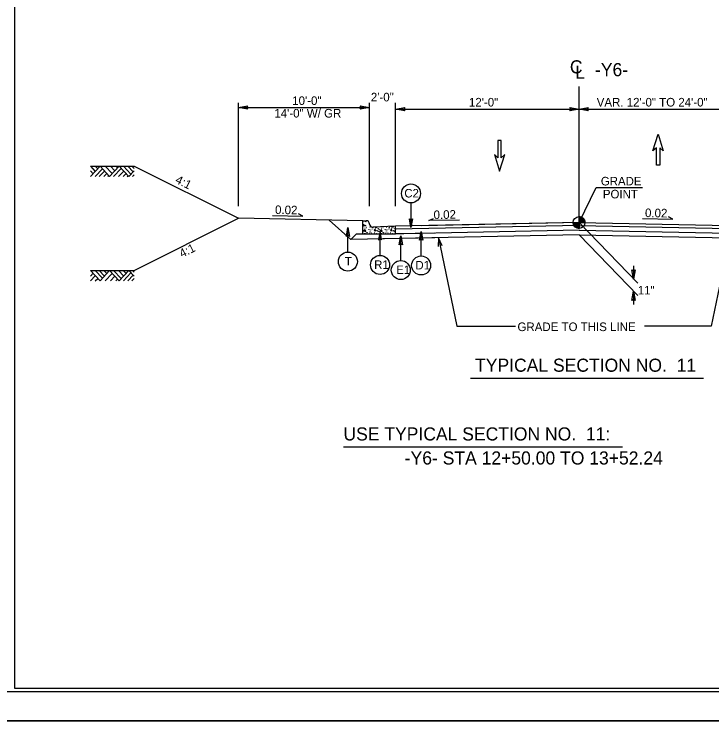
# Model space of a CAD drawing. Extents: x 1901670 to 1902225, y 193498 to 194278.
# Drawn here: x 1901982.5 to 1902035.7, y 193606.9 to 193661.9 of the extents above; entities that cross this region are included whole.
import ezdxf

# ---------------------------------------------------------------- set-up
doc = ezdxf.new("R2010")
doc.units = 0
for name, color, linetype in [('Old_Level_1', 7, 'Continuous'), ('Old_Level_11', 7, 'Continuous'), ('Old_Level_2', 7, 'Continuous'), ('Old_Level_20', 7, 'Continuous'), ('Prop Dimension', 7, 'Continuous'), ('Sheet Border Standard 30in CELL', 7, 'Continuous'), ('Sheet Cutting Line CELL', 7, 'Continuous'), ('Sheet Plot Border Inside CELL', 7, 'Continuous'), ('Sheet Plot Border Outside CELL', 7, 'Continuous'), ('Typical Curb CELL', 7, 'Continuous'), ('Typical Pavement Slope CELL', 7, 'Continuous'), ('Typical Terminator CELL', 7, 'Continuous'), ('Typical Text Grade Point CELL', 7, 'Continuous')]:
    doc.layers.add(name, color=color, linetype=linetype)

# ---------------------------------------------------------------- blocks, each defined once
blk = doc.blocks.new('TERMINATOR')
at = {"layer": 'Typical Terminator CELL'}
blk.add_lwpolyline([(-0.469, 0.081), (0, 0), (-0.471, -0.083), (-0.411, 0)], close=True, dxfattribs=at)

msp = doc.modelspace()

# ---------------------------------------------------------------- linework, layer by layer
at = {"layer": 'Old_Level_1'}
for p, q in [((1902025.621, 193646.02), (1902025.621, 193656.4)), ((1901988.322, 193650.325), (1901988.697, 193649.922)), ((1901988.322, 193649.52), (1901989.064, 193650.317)), ((1901988.696, 193649.52), (1901989.25, 193650.116)), ((1901988.697, 193650.325), (1901988.884, 193650.124)), ((1901989.064, 193650.317), (1901989.788, 193649.538)), ((1901989.455, 193650.325), (1901989.988, 193649.752)), ((1901989.788, 193649.538), (1901990.519, 193650.324)), ((1901989.853, 193650.325), (1901990.186, 193649.966)), ((1901990.098, 193649.52), (1901990.684, 193650.148)), ((1901990.255, 193650.325), (1901990.388, 193650.182)), ((1901990.519, 193650.324), (1901991.26, 193649.528)), ((1901990.841, 193650.325), (1901991.421, 193649.702)), ((1901991.174, 193650.325), (1901991.588, 193649.881)), ((1901991.494, 193650.325), (1901991.664, 193650.142)), ((1901988.322, 193649.963), (1901988.528, 193649.741)), ((1901989.005, 193649.52), (1901989.406, 193649.949)), ((1901989.352, 193649.52), (1901989.579, 193649.763)), ((1901989.663, 193649.52), (1901989.734, 193649.596)), ((1901990.468, 193649.52), (1901990.868, 193649.949)), ((1901990.834, 193649.52), (1901991.051, 193649.753)), ((1901991.129, 193649.52), (1901991.198, 193649.594)), ((1901991.26, 193649.528), (1901991.664, 193649.963)), ((1901991.53, 193649.52), (1901991.664, 193649.663)), ((1902002.236, 193646.566), (1902004.551, 193646.517)), ((1902004.551, 193646.517), (1902004.218, 193646.684)), ((1902006.54, 193646.208), (1902008.199, 193644.724)), ((1902014.167, 193646.163), (1902014.5, 193646.33)), ((1902016.483, 193646.211), (1902014.167, 193646.163)), ((1902025.621, 193646.02), (1902025.621, 193646.47)), ((1902030.469, 193646.331), (1902032.784, 193646.283)), ((1902032.784, 193646.283), (1902032.451, 193646.45)), ((1902025.621, 193646.02), (1902011.621, 193645.74)), ((1902025.621, 193645.801), (1902011.621, 193645.521)), ((1902025.621, 193646.02), (1902013.621, 193645.78)), ((1902025.171, 193646.02), (1902025.621, 193646.02)), ((1902025.62, 193645.57), (1902025.621, 193646.02)), ((1902025.621, 193646.02), (1902025.62, 193645.57)), ((1902026.071, 193646.02), (1902025.621, 193646.02)), ((1902025.621, 193646.02), (1902037.616, 193645.78)), ((1902025.621, 193646.02), (1902030.096, 193641.383)), ((1902025.621, 193645.801), (1902039.84, 193645.517)), ((1902008.622, 193645.147), (1902008.199, 193644.724)), ((1902008.622, 193645.147), (1902009.122, 193645.157)), ((1902025.621, 193645.437), (1902011.026, 193645.145)), ((1902014.623, 193645.217), (1902011.621, 193645.157)), ((1902025.621, 193645.437), (1902040.211, 193645.145)), ((1902014.623, 193644.853), (1902008.199, 193644.724)), ((1902025.621, 193645.073), (1902010.654, 193644.773)), ((1902025.621, 193645.073), (1902040.583, 193644.773)), ((1902025.621, 193645.073), (1902030.098, 193640.448)), ((1901988.322, 193642.368), (1901989.064, 193641.571)), ((1901988.696, 193642.368), (1901989.25, 193641.772)), ((1901989.005, 193642.368), (1901989.406, 193641.939)), ((1901989.064, 193641.571), (1901989.788, 193642.35)), ((1901989.352, 193642.368), (1901989.579, 193642.125)), ((1901989.663, 193642.368), (1901989.734, 193642.292)), ((1901989.788, 193642.35), (1901990.519, 193641.564)), ((1901990.098, 193642.368), (1901990.684, 193641.74)), ((1901990.468, 193642.368), (1901990.868, 193641.939)), ((1901990.519, 193641.564), (1901991.26, 193642.36)), ((1901990.834, 193642.368), (1901991.051, 193642.135)), ((1901991.129, 193642.368), (1901991.198, 193642.294)), ((1901991.26, 193642.36), (1901991.664, 193641.925)), ((1901991.53, 193642.368), (1901991.664, 193642.225)), ((1902029.777, 193642.712), (1902029.777, 193641.712)), ((1901988.322, 193641.925), (1901988.528, 193642.147)), ((1901988.322, 193641.563), (1901988.697, 193641.966)), ((1901989.455, 193641.563), (1901989.988, 193642.136)), ((1901989.853, 193641.563), (1901990.186, 193641.922)), ((1901990.841, 193641.563), (1901991.421, 193642.186)), ((1901991.174, 193641.563), (1901991.588, 193642.007)), ((1901988.697, 193641.563), (1901988.884, 193641.764)), ((1901990.255, 193641.563), (1901990.388, 193641.706)), ((1901991.494, 193641.563), (1901991.664, 193641.746)), ((1902029.779, 193640.777), (1902029.779, 193639.777))]:
    msp.add_line(p, q, dxfattribs=at)
for points in [[(1902025.625, 193646.47), (1902025.625, 193646.47), (1902025.625, 193646.02)], [(1902025.634, 193646.47), (1902025.634, 193646.02)], [(1902025.643, 193646.469), (1902025.643, 193646.02)], [(1902025.652, 193646.469), (1902025.652, 193646.02)], [(1902025.661, 193646.468), (1902025.661, 193646.02)], [(1902025.67, 193646.467), (1902025.67, 193646.02)], [(1902025.679, 193646.466), (1902025.679, 193646.02)], [(1902025.688, 193646.465), (1902025.688, 193646.02)], [(1902025.697, 193646.464), (1902025.697, 193646.02)], [(1902025.706, 193646.462), (1902025.706, 193646.02)], [(1902025.715, 193646.46), (1902025.715, 193646.02)], [(1902025.724, 193646.458), (1902025.724, 193646.02)], [(1902025.733, 193646.456), (1902025.733, 193646.02)], [(1902025.742, 193646.453), (1902025.742, 193646.02)], [(1902025.751, 193646.451), (1902025.751, 193646.02)], [(1902025.76, 193646.448), (1902025.76, 193646.02)], [(1902025.769, 193646.445), (1902025.769, 193646.02)], [(1902025.778, 193646.442), (1902025.778, 193646.02)], [(1902025.787, 193646.438), (1902025.787, 193646.02)], [(1902025.796, 193646.434), (1902025.796, 193646.02)], [(1902025.805, 193646.43), (1902025.805, 193646.02)], [(1902025.814, 193646.426), (1902025.814, 193646.02)], [(1902025.823, 193646.422), (1902025.823, 193646.02)], [(1902025.832, 193646.417), (1902025.832, 193646.02)], [(1902025.841, 193646.412), (1902025.841, 193646.02)], [(1902025.85, 193646.407), (1902025.85, 193646.02)], [(1902025.859, 193646.402), (1902025.859, 193646.02)], [(1902025.868, 193646.396), (1902025.868, 193646.02)], [(1902025.877, 193646.39), (1902025.877, 193646.02)], [(1902025.886, 193646.383), (1902025.886, 193646.02)], [(1902025.895, 193646.377), (1902025.895, 193646.02)], [(1902025.904, 193646.37), (1902025.904, 193646.02)], [(1902025.913, 193646.362), (1902025.913, 193646.02)], [(1902025.922, 193646.354), (1902025.922, 193646.02)], [(1902025.931, 193646.346), (1902025.931, 193646.02)], [(1902025.94, 193646.337), (1902025.94, 193646.02)], [(1902025.949, 193646.328), (1902025.949, 193646.02)], [(1902025.958, 193646.318), (1902025.958, 193646.02)], [(1902025.967, 193646.307), (1902025.967, 193646.02)], [(1902025.976, 193646.296), (1902025.976, 193646.02)], [(1902025.985, 193646.284), (1902025.985, 193646.02)], [(1902025.994, 193646.271), (1902025.994, 193646.02)], [(1902026.003, 193646.257), (1902026.003, 193646.02)], [(1902026.012, 193646.242), (1902026.012, 193646.02)], [(1902026.021, 193646.226), (1902026.021, 193646.02)], [(1902026.03, 193646.207), (1902026.03, 193646.02)], [(1902025.173, 193646.02), (1902025.173, 193645.971)], [(1902025.182, 193646.02), (1902025.182, 193645.918)], [(1902025.191, 193646.02), (1902025.191, 193645.886)], [(1902025.2, 193646.02), (1902025.2, 193645.859)], [(1902025.209, 193646.02), (1902025.209, 193645.838)], [(1902025.218, 193646.02), (1902025.218, 193645.819)], [(1902025.227, 193646.02), (1902025.227, 193645.802)], [(1902025.236, 193646.02), (1902025.236, 193645.786)], [(1902025.245, 193646.02), (1902025.245, 193645.772)], [(1902025.254, 193646.02), (1902025.254, 193645.759)], [(1902025.263, 193646.02), (1902025.263, 193645.747)], [(1902025.272, 193646.02), (1902025.272, 193645.736)], [(1902025.281, 193646.02), (1902025.281, 193645.725)], [(1902025.29, 193646.02), (1902025.29, 193645.715)], [(1902025.299, 193646.02), (1902025.299, 193645.705)], [(1902025.308, 193646.02), (1902025.308, 193645.696)], [(1902025.317, 193646.02), (1902025.317, 193645.688)], [(1902025.326, 193646.02), (1902025.326, 193645.68)], [(1902025.335, 193646.02), (1902025.335, 193645.672)], [(1902025.344, 193646.02), (1902025.344, 193645.665)], [(1902025.353, 193646.02), (1902025.353, 193645.658)], [(1902025.362, 193646.02), (1902025.362, 193645.652)], [(1902025.371, 193646.02), (1902025.371, 193645.646)], [(1902025.38, 193646.02), (1902025.38, 193645.64)], [(1902025.389, 193646.02), (1902025.389, 193645.634)], [(1902025.398, 193646.02), (1902025.398, 193645.629)], [(1902025.407, 193646.02), (1902025.407, 193645.624)], [(1902025.416, 193646.02), (1902025.416, 193645.619)], [(1902025.425, 193646.02), (1902025.425, 193645.615)], [(1902025.434, 193646.02), (1902025.434, 193645.611)], [(1902025.443, 193646.02), (1902025.443, 193645.607)], [(1902025.452, 193646.02), (1902025.452, 193645.603)], [(1902025.461, 193646.02), (1902025.461, 193645.599)], [(1902025.47, 193646.02), (1902025.47, 193645.596)], [(1902025.479, 193646.02), (1902025.479, 193645.593)], [(1902025.488, 193646.02), (1902025.488, 193645.59)], [(1902025.497, 193646.02), (1902025.497, 193645.588)], [(1902025.506, 193646.02), (1902025.506, 193645.585)], [(1902025.515, 193646.02), (1902025.515, 193645.583)], [(1902025.524, 193646.02), (1902025.524, 193645.581)], [(1902025.533, 193646.02), (1902025.533, 193645.579)], [(1902025.542, 193646.02), (1902025.542, 193645.577)], [(1902025.551, 193646.02), (1902025.551, 193645.576)], [(1902025.56, 193646.02), (1902025.56, 193645.574)], [(1902025.569, 193646.02), (1902025.569, 193645.573)], [(1902025.578, 193646.02), (1902025.578, 193645.572)], [(1902025.587, 193646.02), (1902025.587, 193645.571)], [(1902025.596, 193646.02), (1902025.596, 193645.571)], [(1902025.605, 193646.02), (1902025.605, 193645.57)], [(1902025.614, 193646.02), (1902025.614, 193645.57), (1902025.614, 193645.57)], [(1902026.039, 193646.186), (1902026.039, 193646.02)], [(1902026.048, 193646.161), (1902026.048, 193646.02)], [(1902026.057, 193646.13), (1902026.057, 193646.02)], [(1902026.066, 193646.084), (1902026.066, 193646.02)], [(1902015.184, 193644.249), (1902014.891, 193644.858), (1902014.863, 193644.182)], [(1902014.891, 193644.858), (1902016.303, 193638.106), (1902020.775, 193638.106)], [(1902037.096, 193644.834), (1902035.689, 193638.106), (1902030.602, 193638.106)]]:
    msp.add_lwpolyline(points, dxfattribs=at)
msp.add_circle((1902025.621, 193646.02), 0.45, dxfattribs=at)
for start, end in [(359.9905, 89.9905), (179.9905, 269.9905)]:
    msp.add_arc((1902025.621, 193646.02), 0.45, start, end, dxfattribs=at)
at = {"layer": 'Old_Level_11'}
for p, q in [((1902012.793, 193647.513), (1902012.793, 193645.639)), ((1902007.975, 193643.764), (1902007.975, 193645.638)), ((1902010.43, 193643.511), (1902010.43, 193645.385)), ((1902013.565, 193643.469), (1902013.565, 193645.344)), ((1902012.014, 193643.12), (1902012.014, 193644.995)), ((1902017.328, 193634.145), (1902035.127, 193634.145)), ((1902007.638, 193628.903), (1902028.934, 193628.903))]:
    msp.add_line(p, q, dxfattribs=at)
for points in [[(1902012.909, 193646.311), (1902012.793, 193645.639), (1902012.674, 193646.314), (1902012.793, 193646.229)], [(1902007.86, 193644.967), (1902007.975, 193645.638), (1902008.095, 193644.963), (1902007.975, 193645.049)], [(1902010.545, 193644.713), (1902010.43, 193645.385), (1902010.31, 193644.71), (1902010.43, 193644.795)], [(1902013.449, 193644.672), (1902013.565, 193645.344), (1902013.684, 193644.668), (1902013.565, 193644.754)], [(1902011.899, 193644.323), (1902012.014, 193644.995), (1902012.134, 193644.319), (1902012.014, 193644.405)]]:
    msp.add_lwpolyline(points, close=True, dxfattribs=at)
for centre in [(1902012.793, 193648.239), (1902007.975, 193643.039), (1902010.43, 193642.786), (1902013.565, 193642.744), (1902012.014, 193642.395)]:
    msp.add_circle(centre, 0.725, dxfattribs=at)
at = {"layer": 'Prop Dimension'}
for p, q in [((1901999.621, 193647.278), (1901999.621, 193655.16)), ((1902009.621, 193647.278), (1902009.621, 193655.16)), ((1902011.621, 193647.268), (1902011.621, 193655.15)), ((1901999.621, 193654.79), (1902009.621, 193654.79)), ((1902011.621, 193654.67), (1902025.621, 193654.67)), ((1902013.621, 193654.67), (1902025.621, 193654.67)), ((1902025.616, 193654.67), (1902037.616, 193654.67))]:
    msp.add_line(p, q, dxfattribs=at)
for points in [[(1902019.945, 193651.2), (1902019.675, 193650.95), (1902019.675, 193652.284), (1902019.425, 193652.284), (1902019.425, 193650.95), (1902019.154, 193651.2), (1902019.55, 193649.929)], [(1902019.945, 193651.2), (1902019.675, 193650.95), (1902019.675, 193652.284), (1902019.425, 193652.284), (1902019.425, 193650.95), (1902019.154, 193651.2), (1902019.55, 193649.929)], [(1902032.042, 193651.479), (1902031.771, 193651.729), (1902031.771, 193650.395), (1902031.521, 193650.395), (1902031.521, 193651.729), (1902031.25, 193651.479), (1902031.646, 193652.749)], [(1902032.042, 193651.479), (1902031.771, 193651.729), (1902031.771, 193650.395), (1902031.521, 193650.395), (1902031.521, 193651.729), (1902031.25, 193651.479), (1902031.646, 193652.749)]]:
    msp.add_lwpolyline(points, close=True, dxfattribs=at)
at = {"layer": 'Sheet Border Standard 30in CELL'}
msp.add_lwpolyline([(1902132.544, 193715.514), (1901982.544, 193715.514), (1901982.544, 193610.514), (1902132.544, 193610.514)], close=True, dxfattribs=at)
at = {"layer": 'Sheet Cutting Line CELL'}
for p, q in [((1901965.844, 193608.014), (1902134.244, 193608.014)), ((1902134.244, 193608.014), (1901965.844, 193608.014))]:
    msp.add_line(p, q, dxfattribs=at)
at = {"layer": 'Sheet Plot Border Inside CELL'}
msp.add_lwpolyline([(1902133.794, 193715.769), (1901967.144, 193715.769), (1901967.144, 193610.259), (1902133.794, 193610.259)], close=True, dxfattribs=at)
at = {"layer": 'Sheet Plot Border Outside CELL'}
for points in [[(1902134.244, 193718.014), (1901965.844, 193718.014), (1901965.844, 193608.014), (1902134.244, 193608.014)], [(1902134.244, 193608.014), (1901965.844, 193608.014), (1901965.844, 193498.014), (1902134.244, 193498.014)]]:
    msp.add_lwpolyline(points, close=True, dxfattribs=at)
at = {"layer": 'Typical Curb CELL'}
for p, q in [((1902009.122, 193645.157), (1902009.122, 193646.157)), ((1902009.122, 193646.157), (1902009.382, 193646.157)), ((1902009.158, 193645.779), (1902009.312, 193645.823)), ((1902009.296, 193645.733), (1902009.158, 193645.779)), ((1902009.312, 193645.823), (1902009.296, 193645.733)), ((1902009.621, 193645.907), (1902009.621, 193645.917)), ((1902011.621, 193645.74), (1902009.871, 193645.667)), ((1902011.621, 193645.157), (1902011.621, 193645.74)), ((1902009.122, 193645.157), (1902011.621, 193645.157)), ((1902009.284, 193645.46), (1902009.181, 193645.385)), ((1902009.181, 193645.385), (1902009.347, 193645.345)), ((1902009.347, 193645.345), (1902009.284, 193645.46)), ((1902010.026, 193645.516), (1902009.991, 193645.403)), ((1902009.991, 193645.403), (1902010.111, 193645.396)), ((1902010.111, 193645.396), (1902010.026, 193645.516)), ((1902010.533, 193645.46), (1902010.43, 193645.385)), ((1902010.43, 193645.385), (1902010.595, 193645.345)), ((1902010.595, 193645.345), (1902010.533, 193645.46)), ((1902011.274, 193645.516), (1902011.24, 193645.403)), ((1902011.24, 193645.403), (1902011.361, 193645.396)), ((1902011.361, 193645.396), (1902011.274, 193645.516))]:
    msp.add_line(p, q, dxfattribs=at)
for centre in [(1902009.135, 193646.047), (1902009.186, 193645.864), (1902009.352, 193646.081), (1902009.66, 193645.67), (1902010.174, 193645.651), (1902010.909, 193645.67), (1902011.28, 193645.698), (1902011.423, 193645.681), (1902009.266, 193645.203), (1902009.283, 193645.591), (1902009.403, 193645.641), (1902009.438, 193645.243), (1902009.58, 193645.477), (1902009.615, 193645.18), (1902009.672, 193645.294), (1902009.677, 193645.62), (1902009.706, 193645.448), (1902009.786, 193645.208), (1902009.854, 193645.534), (1902009.883, 193645.636), (1902009.991, 193645.231), (1902010.077, 193645.597), (1902010.151, 193645.163), (1902010.202, 193645.397), (1902010.282, 193645.557), (1902010.299, 193645.351), (1902010.338, 193645.591), (1902010.356, 193645.494), (1902010.361, 193645.186), (1902010.515, 193645.203), (1902010.533, 193645.591), (1902010.652, 193645.641), (1902010.687, 193645.243), (1902010.829, 193645.477), (1902010.864, 193645.18), (1902010.921, 193645.294), (1902010.926, 193645.62), (1902010.955, 193645.448), (1902011.035, 193645.208), (1902011.103, 193645.534), (1902011.132, 193645.636), (1902011.24, 193645.231), (1902011.326, 193645.597), (1902011.4, 193645.163), (1902011.451, 193645.397), (1902011.532, 193645.557), (1902011.548, 193645.351), (1902011.588, 193645.591), (1902011.605, 193645.494), (1902011.61, 193645.186)]:
    msp.add_circle(centre, 0.00802, dxfattribs=at)
for centre, start, end in [((1902009.382, 193645.917), 0.0002, 90.0002), ((1902009.861, 193645.907), 180.0002, 272.3846)]:
    msp.add_arc(centre, 0.24, start, end, dxfattribs=at)
at = {"layer": 'Typical Pavement Slope CELL'}
for p in [(1901991.664, 193650.325), (1901991.664, 193642.368), (1902009.122, 193646.157)]:
    msp.add_line(p, (1901999.621, 193646.347), dxfattribs=at)
for points in [[(1901988.322, 193650.325), (1901991.664, 193650.325)], [(1901988.322, 193642.368), (1901991.664, 193642.368)]]:
    msp.add_lwpolyline(points, dxfattribs=at)
at = {"layer": 'Typical Text Grade Point CELL'}
for p, q in [((1902025.621, 193646.02), (1902026.917, 193648.693)), ((1902026.917, 193648.693), (1902030.455, 193648.693))]:
    msp.add_line(p, q, dxfattribs=at)

# ---------------------------------------------------------------- block references
at = {"layer": 'Old_Level_1', "xscale": 1.5, "yscale": 1.5}
for p, rotation in [((1902029.777, 193641.712), -90), ((1902029.779, 193640.777), 90)]:
    msp.add_blockref('TERMINATOR', p, dxfattribs=dict(at, rotation=rotation))
at = {"layer": 'Prop Dimension', "xscale": 1.5, "yscale": 1.5, "rotation": 180}
for p in [(1901999.621, 193654.79), (1902011.621, 193654.67), (1902025.616, 193654.67)]:
    msp.add_blockref('TERMINATOR', p, dxfattribs=at)
at = {"layer": 'Prop Dimension', "xscale": 1.5, "yscale": 1.5}
for p in [(1902009.621, 193654.79), (1902025.621, 193654.67)]:
    msp.add_blockref('TERMINATOR', p, dxfattribs=at)

# ---------------------------------------------------------------- texts
at = {"layer": 'Old_Level_1'}
for rotation, p in [(333.4349, (1901994.747, 193649.074)), (26.5651, (1901995.313, 193643.319))]:
    msp.add_text('4:1', height=0.656, rotation=rotation, dxfattribs=at).set_placement(p)
for s, height, p in [('11"', 0.6491, (1902030.103, 193640.537)), ('GRADE TO THIS LINE', 0.656, (1902020.919, 193637.74))]:
    msp.add_text(s, height=height, dxfattribs=at).set_placement(p)
at = {"layer": 'Old_Level_11'}
for s, p in [('TYPICAL SECTION NO.  11', (1902017.684, 193634.639)), ('USE TYPICAL SECTION NO.  11:', (1902007.638, 193629.397)), ('-Y6- STA 12+50.00 TO 13+52.24 ', (1902012.314, 193627.565))]:
    msp.add_text(s, height=1, dxfattribs=at).set_placement(p)
at = {"layer": 'Old_Level_2'}
msp.add_text('C', height=1, dxfattribs=at).set_placement((1902024.919, 193657.395))
for s, height, rotation, p in [('L', 1, 359.9469, (1902025.321, 193656.991)), ('-Y6-', 1, 359.9469, (1902026.836, 193657.182)), ('0.02', 0.656, 358.8084, (1902002.413, 193646.673)), ('0.02', 0.656, 1.1916, (1902014.523, 193646.281)), ('0.02', 0.656, 358.8084, (1902030.646, 193646.438))]:
    msp.add_text(s, height=height, rotation=rotation, dxfattribs=at).set_placement(p)
at = {"layer": 'Old_Level_20'}
for s, height, p in [('C2', 0.6491, (1902012.287, 193647.932)), ('T', 0.649, (1902007.748, 193642.746)), ('R1', 0.6491, (1902009.984, 193642.482)), ('D1', 0.6491, (1902013.132, 193642.441)), ('E1', 0.6491, (1902011.669, 193642.092))]:
    msp.add_text(s, height=height, dxfattribs=at).set_placement(p)
at = {"layer": 'Prop Dimension'}
for s, p in [('10\'-0" ', (1902003.728, 193654.988)), ('2\'-0" ', (1902009.73, 193655.259)), ('12\'-0" ', (1902017.215, 193654.868)), ('VAR. 12\'-0" TO 24\'-0" ', (1902026.965, 193654.868)), ('14\'-0" W/ GR ', (1902002.366, 193654.027))]:
    msp.add_text(s, height=0.656, dxfattribs=at).set_placement(p)
at = {"layer": 'Typical Text Grade Point CELL'}
for s, p in [('GRADE', (1902027.281, 193648.849)), ('POINT', (1902027.438, 193647.861))]:
    msp.add_text(s, height=0.6525, dxfattribs=at).set_placement(p)

doc.saveas('drawing.dxf')
